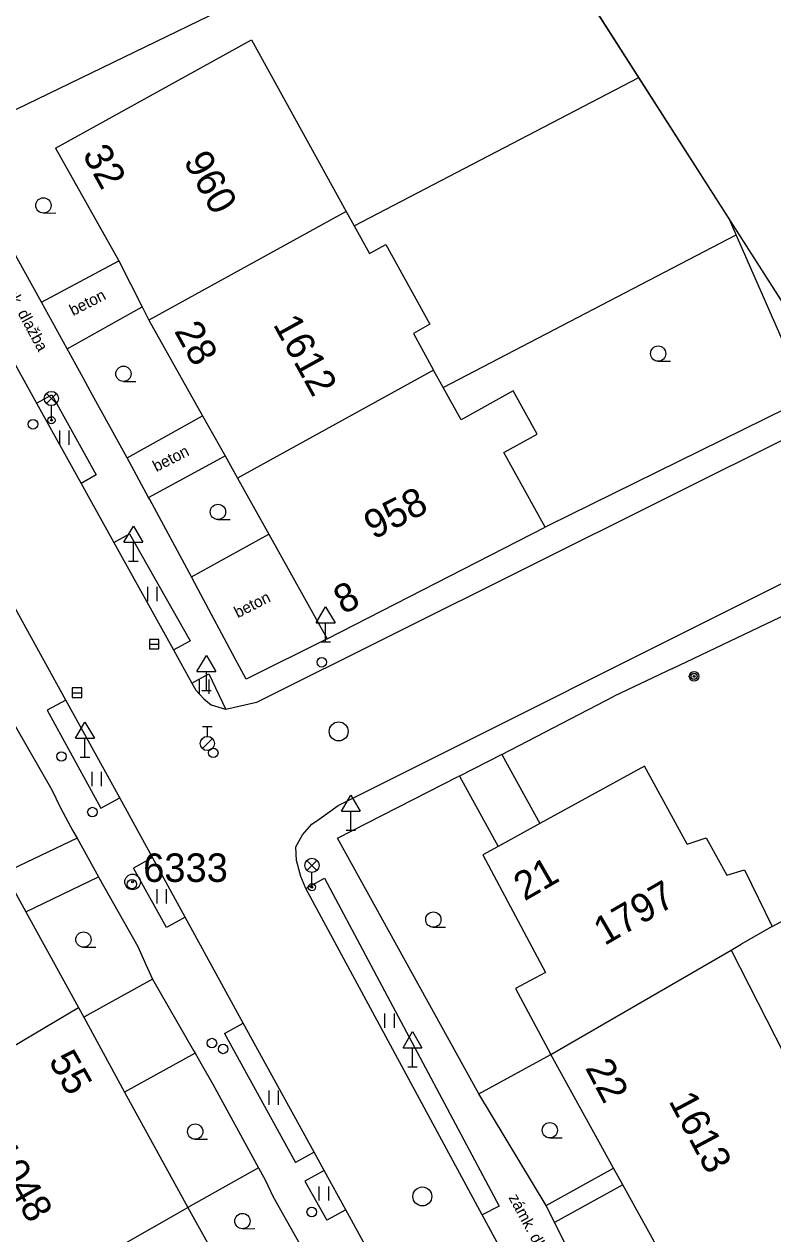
# Model space of a CAD drawing. Extents: x -493753 to -49290, y -1127285 to -112654.
# Drawn here: x -492916.9 to -492877.4, y -1126699.8 to -1126636 of the extents above; entities that cross this region are included whole.
import ezdxf

# ---------------------------------------------------------------- set-up
doc = ezdxf.new("R2010")
doc.units = 0
for name, color, linetype in [('Vrstva 1', 7, 'Continuous'), ('Vrstva 10', 7, 'Continuous'), ('Vrstva 11', 7, 'Continuous'), ('Vrstva 25', 7, 'Continuous'), ('Vrstva 27', 7, 'Continuous'), ('Vrstva 28', 7, 'Continuous'), ('Vrstva 31', 7, 'Continuous'), ('Vrstva 33', 7, 'Continuous'), ('Vrstva 34', 7, 'Continuous'), ('Vrstva 36', 7, 'Continuous'), ('Vrstva 40', 7, 'Continuous'), ('Vrstva 43', 7, 'Continuous'), ('Vrstva 44', 7, 'Continuous'), ('Vrstva 5', 7, 'Continuous'), ('Vrstva 60', 7, 'Continuous'), ('Vrstva 63', 7, 'Continuous'), ('Vrstva 7', 7, 'Continuous'), ('Vrstva 8', 7, 'Continuous')]:
    doc.layers.add(name, color=color, linetype=linetype)

msp = doc.modelspace()

# ---------------------------------------------------------------- linework, layer by layer
at = {"layer": 'Vrstva 1'}
msp.add_lwpolyline([(-493753.129, -1126773.634), (-493540.881, -1127284.865), (-492737.61, -1126868.64), (-492950.39, -1126535.73)], dxfattribs=at)
at = {"layer": 'Vrstva 10'}
for p, q in [((-492875.01, -1126656.98), (-492904.65, -1126671.75)), ((-492900.33, -1126677.19), (-492869.759, -1126661.883)), ((-492912.16, -1126663.33), (-492911.33, -1126662.87)), ((-492911.33, -1126662.87), (-492908.14, -1126668.5)), ((-492909.02, -1126668.99), (-492908.14, -1126668.5)), ((-492908.05, -1126670.74), (-492907.16, -1126670.24)), ((-492907.16, -1126670.24), (-492906.26, -1126672.12)), ((-492908.05, -1126670.74), (-492907.84, -1126671.1)), ((-492914.69, -1126671.63), (-492915.67, -1126672.17)), ((-492907.84, -1126671.1), (-492907.42, -1126671.57)), ((-492907.42, -1126671.57), (-492907.02, -1126671.9)), ((-492915.67, -1126672.17), (-492912.85, -1126677.33)), ((-492906.26, -1126672.12), (-492907.02, -1126671.9)), ((-492904.65, -1126671.75), (-492906.26, -1126672.12)), ((-492912.85, -1126677.33), (-492911.85, -1126676.78)), ((-492901.34, -1126677.91), (-492900.33, -1126677.19)), ((-492901.72, -1126678.16), (-492901.34, -1126677.91)), ((-492902.22, -1126678.73), (-492901.72, -1126678.16)), ((-492902.56, -1126679.37), (-492902.22, -1126678.73)), ((-492910.12, -1126679.93), (-492911.12, -1126680.48)), ((-492902.54, -1126680.09), (-492902.56, -1126679.37)), ((-492909.39, -1126683.61), (-492911.12, -1126680.48)), ((-492902.31, -1126680.93), (-492902.54, -1126680.09)), ((-492902.04, -1126681.55), (-492902.31, -1126680.93)), ((-492908.4, -1126683.07), (-492909.39, -1126683.61)), ((-492906.32, -1126689.2), (-492905.34, -1126688.66)), ((-492906.32, -1126689.2), (-492902.59, -1126695.99)), ((-492901.61, -1126695.45), (-492902.59, -1126695.99)), ((-492901.07, -1126696.42), (-492902.09, -1126696.98)), ((-492902.09, -1126696.98), (-492900.94, -1126699.04)), ((-492899.94, -1126698.49), (-492900.94, -1126699.04))]:
    msp.add_line(p, q, dxfattribs=at)
for points in [[(-492925.14, -1126639.93), (-492923.11, -1126643.6), (-492919, -1126651.02), (-492916.24, -1126655.99), (-492913.89, -1126660.22), (-492912.16, -1126663.33), (-492909.02, -1126668.99), (-492908.05, -1126670.74)], [(-492915.98, -1126650.67), (-492911.9, -1126648.48)], [(-492914.62, -1126653.12), (-492910.66, -1126650.92)], [(-492916.24, -1126655.99), (-492915.43, -1126655.55), (-492913.09, -1126659.77), (-492913.89, -1126660.22)], [(-492911.46, -1126658.87), (-492907.48, -1126656.66)], [(-492911.85, -1126676.78), (-492914.69, -1126671.63), (-492916.97, -1126667.49), (-492921.17, -1126659.86), (-492921.82, -1126658.67)], [(-492910.33, -1126660.96), (-492906.3, -1126658.77)], [(-492908.07, -1126665.14), (-492904, -1126662.88)], [(-492891.71, -1126674.5), (-492889.71, -1126678.14)], [(-492893.94, -1126675.63), (-492891.9, -1126679.34)], [(-492905.34, -1126688.66), (-492908.4, -1126683.07), (-492910.12, -1126679.93), (-492911.85, -1126676.78)], [(-492916.8, -1126682.79), (-492912.97, -1126680.95)], [(-492902.04, -1126681.55), (-492901.06, -1126681.02)], [(-492901.06, -1126681.02), (-492891.86, -1126698.29), (-492892.74, -1126698.75)], [(-492884.7, -1126713.61), (-492890.74, -1126702.44), (-492892.74, -1126698.75), (-492902.04, -1126681.55)], [(-492896.61, -1126704.54), (-492899.94, -1126698.49), (-492901.07, -1126696.42), (-492901.61, -1126695.45), (-492905.34, -1126688.66)], [(-492889.38, -1126698.26), (-492885.82, -1126696.29)], [(-492885.33, -1126697.17), (-492888.93, -1126699.16)]]:
    msp.add_lwpolyline(points, dxfattribs=at)
at = {"layer": 'Vrstva 11'}
for points in [[(-492899.5, -1126646.64), (-492884.498, -1126638.823)], [(-492894.8, -1126655.16), (-492879.36, -1126647.11)], [(-492877.46, -1126683.56), (-492865.21, -1126676.95)]]:
    msp.add_lwpolyline(points, dxfattribs=at)
at = {"layer": 'Vrstva 25'}
for radius in [0.25, 0.158, 0.05]:
    msp.add_circle((-492881.58, -1126670.38), radius, dxfattribs=at)
at = {"layer": 'Vrstva 27'}
for p, q in [((-492910.28, -1126668.68), (-492909.78, -1126668.68)), ((-492914.35, -1126671.24), (-492913.85, -1126671.24))]:
    msp.add_line(p, q, dxfattribs=at)
for points in [[(-492910.28, -1126668.93), (-492909.78, -1126668.93), (-492909.78, -1126668.43), (-492910.28, -1126668.43)], [(-492914.35, -1126671.49), (-492913.85, -1126671.49), (-492913.85, -1126670.99), (-492914.35, -1126670.99)]]:
    msp.add_lwpolyline(points, close=True, dxfattribs=at)
for centre in [(-492900.31, -1126673.28), (-492895.9, -1126697.78)]:
    msp.add_circle(centre, 0.5, dxfattribs=at)
at = {"layer": 'Vrstva 28'}
for p, q in [((-492907.48, -1126673.02), (-492906.98, -1126673.02)), ((-492907.23, -1126673.545), (-492907.23, -1126673.02)), ((-492907.495, -1126674.185), (-492906.965, -1126673.655))]:
    msp.add_line(p, q, dxfattribs=at)
for centre, radius in [((-492916.42, -1126657.1), 0.25), ((-492907.23, -1126673.92), 0.375), ((-492906.92, -1126674.41), 0.25), ((-492914.92, -1126674.6), 0.25), ((-492913.29, -1126677.53), 0.25), ((-492911.21, -1126681.33), 0.25), ((-492906.99, -1126689.7), 0.25), ((-492906.4, -1126690.01), 0.25), ((-492901.73, -1126698.6), 0.25)]:
    msp.add_circle(centre, radius, dxfattribs=at)
at = {"layer": 'Vrstva 31'}
msp.add_circle((-492901.2, -1126669.64), 0.25, dxfattribs=at)
at = {"layer": 'Vrstva 33'}
for p, q in [((-492915.715, -1126655.475), (-492915.185, -1126656.005)), ((-492915.715, -1126656.005), (-492915.185, -1126655.475)), ((-492915.45, -1126656.89), (-492915.45, -1126656.115)), ((-492901.985, -1126680.075), (-492901.455, -1126680.605)), ((-492901.985, -1126680.605), (-492901.455, -1126680.075)), ((-492901.72, -1126681.49), (-492901.72, -1126680.715))]:
    msp.add_line(p, q, dxfattribs=at)
for centre, radius in [((-492915.45, -1126655.74), 0.375), ((-492915.45, -1126656.89), 0.19), ((-492915.45, -1126656.89), 0.05), ((-492901.72, -1126680.34), 0.375), ((-492901.72, -1126681.49), 0.19), ((-492901.72, -1126681.49), 0.05)]:
    msp.add_circle(centre, radius, dxfattribs=at)
at = {"layer": 'Vrstva 34'}
for p, q in [((-492911.63, -1126663.31), (-492911.13, -1126662.46)), ((-492911.13, -1126662.46), (-492910.63, -1126663.31)), ((-492911.63, -1126663.31), (-492910.63, -1126663.31)), ((-492911.13, -1126664.31), (-492911.13, -1126663.31)), ((-492911.38, -1126664.31), (-492910.88, -1126664.31)), ((-492901.5, -1126667.56), (-492901, -1126666.71)), ((-492901, -1126666.71), (-492900.5, -1126667.56)), ((-492901.5, -1126667.56), (-492900.5, -1126667.56)), ((-492901, -1126668.56), (-492901, -1126667.56)), ((-492901.25, -1126668.56), (-492900.75, -1126668.56)), ((-492907.78, -1126670.13), (-492907.28, -1126669.28)), ((-492907.28, -1126669.28), (-492906.78, -1126670.13)), ((-492907.78, -1126670.13), (-492906.78, -1126670.13)), ((-492907.28, -1126671.13), (-492907.28, -1126670.13)), ((-492907.53, -1126671.13), (-492907.03, -1126671.13)), ((-492914.18, -1126673.64), (-492913.68, -1126672.79)), ((-492913.68, -1126672.79), (-492913.18, -1126673.64)), ((-492914.18, -1126673.64), (-492913.18, -1126673.64)), ((-492913.68, -1126674.64), (-492913.68, -1126673.64)), ((-492913.93, -1126674.64), (-492913.43, -1126674.64)), ((-492900.17, -1126677.49), (-492899.67, -1126676.64)), ((-492899.67, -1126676.64), (-492899.17, -1126677.49)), ((-492900.17, -1126677.49), (-492899.17, -1126677.49)), ((-492899.67, -1126678.49), (-492899.67, -1126677.49)), ((-492899.92, -1126678.49), (-492899.42, -1126678.49)), ((-492896.92, -1126689.95), (-492896.42, -1126689.1)), ((-492896.42, -1126689.1), (-492895.92, -1126689.95)), ((-492896.92, -1126689.95), (-492895.92, -1126689.95)), ((-492896.42, -1126690.95), (-492896.42, -1126689.95)), ((-492896.67, -1126690.95), (-492896.17, -1126690.95))]:
    msp.add_line(p, q, dxfattribs=at)
at = {"layer": 'Vrstva 36'}
for p, q in [((-492915.872, -1126645.97), (-492915.222, -1126645.967)), ((-492883.472, -1126653.78), (-492882.822, -1126653.777)), ((-492911.652, -1126654.84), (-492911.002, -1126654.837)), ((-492915.01, -1126658.18), (-492915.01, -1126657.43)), ((-492914.51, -1126658.18), (-492914.51, -1126657.43)), ((-492906.672, -1126662.12), (-492906.022, -1126662.117)), ((-492910.37, -1126666.42), (-492910.37, -1126665.67)), ((-492909.87, -1126666.42), (-492909.87, -1126665.67)), ((-492907.64, -1126671.3), (-492907.64, -1126670.55)), ((-492907.14, -1126671.3), (-492907.14, -1126670.55)), ((-492913.31, -1126676.16), (-492913.31, -1126675.41)), ((-492912.81, -1126676.16), (-492912.81, -1126675.41)), ((-492909.88, -1126682.34), (-492909.88, -1126681.59)), ((-492909.38, -1126682.34), (-492909.38, -1126681.59)), ((-492895.322, -1126683.6), (-492894.672, -1126683.597)), ((-492913.762, -1126684.65), (-492913.112, -1126684.647)), ((-492897.87, -1126688.9), (-492897.87, -1126688.15)), ((-492897.37, -1126688.9), (-492897.37, -1126688.15)), ((-492903.98, -1126692.95), (-492903.98, -1126692.2)), ((-492903.48, -1126692.95), (-492903.48, -1126692.2)), ((-492907.872, -1126694.77), (-492907.222, -1126694.767)), ((-492889.182, -1126694.7), (-492888.532, -1126694.697)), ((-492901.33, -1126698), (-492901.33, -1126697.25)), ((-492900.83, -1126698), (-492900.83, -1126697.25)), ((-492905.382, -1126699.48), (-492904.732, -1126699.477))]:
    msp.add_line(p, q, dxfattribs=at)
for centre in [(-492915.872, -1126645.567), (-492883.472, -1126653.377), (-492911.652, -1126654.437), (-492906.672, -1126661.717), (-492895.322, -1126683.197), (-492913.762, -1126684.247), (-492889.182, -1126694.297), (-492907.872, -1126694.367), (-492905.382, -1126699.077)]:
    msp.add_circle(centre, 0.403, dxfattribs=at)
at = {"layer": 'Vrstva 5'}
for p, q in [((-492892.71, -1126679.79), (-492889.41, -1126685.98)), ((-492889.41, -1126685.98), (-492890.99, -1126686.82)), ((-492890.99, -1126686.82), (-492889.13, -1126690.31))]:
    msp.add_line(p, q, dxfattribs=at)
for points in [[(-492915.24, -1126642.55), (-492904.91, -1126636.84), (-492899.92, -1126645.88)], [(-492915.24, -1126642.55), (-492911.9, -1126648.48), (-492910.66, -1126650.92), (-492910.31, -1126651.62)], [(-492899.92, -1126645.88), (-492910.31, -1126651.62)], [(-492899.92, -1126645.88), (-492899.5, -1126646.64)], [(-492899.5, -1126646.64), (-492898.69, -1126648.11), (-492897.82, -1126647.62), (-492895.5, -1126651.83), (-492896.37, -1126652.31), (-492895.31, -1126654.24)], [(-492910.31, -1126651.62), (-492907.48, -1126656.66), (-492906.3, -1126658.77), (-492905.64, -1126659.94)], [(-492895.31, -1126654.24), (-492905.64, -1126659.94)], [(-492894.8, -1126655.16), (-492895.31, -1126654.24)], [(-492889.43, -1126662.52), (-492891.6, -1126658.59), (-492889.85, -1126657.62), (-492891.11, -1126655.34), (-492893.86, -1126656.86), (-492894.8, -1126655.16)], [(-492905.64, -1126659.94), (-492904, -1126662.88), (-492900.91, -1126668.41), (-492889.43, -1126662.52)], [(-492884.2, -1126675.11), (-492889.71, -1126678.14), (-492891.9, -1126679.34), (-492892.71, -1126679.79)], [(-492881.95, -1126679.23), (-492884.2, -1126675.11)], [(-492881.95, -1126679.23), (-492880.94, -1126678.89), (-492879.86, -1126680.85), (-492878.92, -1126680.57), (-492877.46, -1126683.56)], [(-492918.36, -1126679.95), (-492917.93, -1126680.74), (-492916.8, -1126682.79), (-492914.03, -1126687.83)], [(-492877.46, -1126683.56), (-492879.09, -1126684.49)], [(-492889.13, -1126690.31), (-492879.62, -1126684.8)], [(-492879.62, -1126684.8), (-492876.84, -1126690.28), (-492876.26, -1126690.09), (-492875.03, -1126692.4), (-492875.41, -1126692.52), (-492872.49, -1126698.27), (-492881.94, -1126703.3), (-492885.33, -1126697.17), (-492885.82, -1126696.29), (-492889.13, -1126690.31)], [(-492879.62, -1126684.8), (-492879.09, -1126684.49)], [(-492924.21, -1126693.86), (-492914.03, -1126687.83)], [(-492914.03, -1126687.83), (-492913.75, -1126688.34), (-492911.59, -1126692.28), (-492908.26, -1126698.37)], [(-492919.68, -1126704.86), (-492908.26, -1126698.37)], [(-492908.26, -1126698.37), (-492906.19, -1126702.09), (-492905.03, -1126704.29), (-492904.56, -1126705.18)]]:
    msp.add_lwpolyline(points, dxfattribs=at)
at = {"layer": 'Vrstva 60'}
msp.add_lwpolyline([(-492991.121, -1127000), (-492737.61, -1126868.64), (-492950.39, -1126535.73), (-493125, -1126587.478)], dxfattribs=at)
at = {"layer": 'Vrstva 63'}
for radius in [0.412, 0.05]:
    msp.add_circle((-492911.17, -1126681.21), radius, dxfattribs=at)
at = {"layer": 'Vrstva 7'}
for points in [[(-492920.71, -1126642.14), (-492905.97, -1126635.02)], [(-492915.98, -1126650.67), (-492918.19, -1126646.69)], [(-492875.58, -1126655.7), (-492879.36, -1126647.11), (-492879.711, -1126646.313)], [(-492913.77, -1126654.66), (-492914.62, -1126653.12)], [(-492874.169, -1126654.983), (-492875.58, -1126655.7), (-492888.11, -1126661.87)], [(-492911.46, -1126658.87), (-492913.28, -1126655.56)], [(-492907.72, -1126665.8), (-492908.07, -1126665.14), (-492910.27, -1126661.06)], [(-492889.25, -1126662.43), (-492889.43, -1126662.52)], [(-492882.72, -1126669.96), (-492871.36, -1126664.55), (-492868.865, -1126663.282)], [(-492900.91, -1126668.41), (-492905.19, -1126670.52), (-492905.76, -1126669.45)], [(-492891.71, -1126674.5), (-492885.8, -1126671.42)], [(-492917.34, -1126673.02), (-492915.43, -1126676.35)], [(-492885.86, -1126705.27), (-492888.93, -1126699.16), (-492889.38, -1126698.26), (-492892.92, -1126692.37), (-492900.38, -1126678.9), (-492894.01, -1126675.66)], [(-492914.97, -1126677.31), (-492914.32, -1126678.52)], [(-492914.1, -1126678.91), (-492917.93, -1126680.74)], [(-492912.94, -1126681.01), (-492910.9, -1126684.61)], [(-492910.47, -1126685.56), (-492910.12, -1126686.33)], [(-492910.12, -1126686.33), (-492913.75, -1126688.34)], [(-492907.96, -1126690.1), (-492907.88, -1126690.23), (-492907.56, -1126690.79)], [(-492907.88, -1126690.23), (-492911.59, -1126692.28)], [(-492892.92, -1126692.37), (-492889.13, -1126690.31)], [(-492906.94, -1126691.87), (-492904.53, -1126696.27)], [(-492904.53, -1126696.27), (-492908.26, -1126698.37)], [(-492904.53, -1126696.27), (-492904.19, -1126696.9)], [(-492903.77, -1126697.81), (-492902.52, -1126700.02), (-492902.35, -1126700.32)]]:
    msp.add_lwpolyline(points, dxfattribs=at)
at = {"layer": 'Vrstva 8'}
for points in [[(-492914.62, -1126653.12), (-492915.98, -1126650.67)], [(-492913.28, -1126655.56), (-492913.77, -1126654.66)], [(-492910.27, -1126661.06), (-492910.33, -1126660.96), (-492911.46, -1126658.87)], [(-492888.11, -1126661.87), (-492889.25, -1126662.43)], [(-492905.76, -1126669.45), (-492907.72, -1126665.8)], [(-492882.72, -1126669.96), (-492885.8, -1126671.42)], [(-492891.71, -1126674.5), (-492893.94, -1126675.63), (-492894.01, -1126675.66)], [(-492915.43, -1126676.35), (-492914.97, -1126677.31)], [(-492914.32, -1126678.52), (-492914.1, -1126678.91), (-492912.97, -1126680.95), (-492912.94, -1126681.01)], [(-492910.9, -1126684.61), (-492910.47, -1126685.56)], [(-492910.12, -1126686.33), (-492907.96, -1126690.1)], [(-492907.56, -1126690.79), (-492906.94, -1126691.87)], [(-492904.19, -1126696.9), (-492903.77, -1126697.81)]]:
    msp.add_lwpolyline(points, dxfattribs=at)

# ---------------------------------------------------------------- texts
at = {"layer": 'Vrstva 40'}
for s, rotation, p in [('zámk. dlažba', 298.24281, (-492918.363, -1126649.158)), ('beton', 27.10411, (-492914.31, -1126651.403)), ('beton', 27.10411, (-492909.92, -1126659.623)), ('beton', 27.10411, (-492905.63, -1126667.323)), ('zámk. dlažba', 298.24281, (-492891.373, -1126697.838))]:
    msp.add_text(s, height=0.6, rotation=rotation, dxfattribs=at).set_placement(p)
at = {"layer": 'Vrstva 43'}
for s, rotation, p in [('960', 298.90597, (-492908.517, -1126643.227)), ('1612', 298.90227, (-492903.795, -1126651.834)), ('958', 27.19061, (-492898.476, -1126663.195)), ('1797', 30.10588, (-492886.303, -1126684.594)), ('1613', 298.02305, (-492882.943, -1126692.749)), ('1048', 299.63237, (-492918.816, -1126695.386))]:
    msp.add_text(s, height=1.5, rotation=rotation, dxfattribs=at).set_placement(p)
at = {"layer": 'Vrstva 44'}
for s, rotation, p in [('32', 298.90597, (-492913.842, -1126642.877)), ('28', 298.90227, (-492909.002, -1126652.186)), ('8', 27.19061, (-492900.074, -1126667.137)), ('21', 30.10588, (-492890.515, -1126682.243)), ('55', 299.63237, (-492915.631, -1126690.623)), ('22', 298.02305, (-492887.34, -1126691.007))]:
    msp.add_text(s, height=1.5, rotation=rotation, dxfattribs=at).set_placement(p)
at = {"layer": 'Vrstva 63'}
msp.add_text(' 6333', height=1.5, dxfattribs=at).set_placement((-492911.17, -1126681.21))

doc.saveas('drawing.dxf')
